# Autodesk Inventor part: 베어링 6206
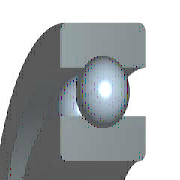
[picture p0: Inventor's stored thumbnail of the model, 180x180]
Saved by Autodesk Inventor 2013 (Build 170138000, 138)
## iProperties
Created: 2009-02
Part Number: 베어링 6206
Material: Steel, Mild
Description: 깊은 그루브 볼 베어링
Document SubType Name: Modeling
Standard: KS B 2023
Designer: KYOUNG IL JANG
Standards Organization: KS
Language: ko-KR
Size Designation: 6206 - 30 x 62 x 16
Categories: <MemberInstance><Categories><Category DisplayName="샤프트 부품" InternalName="7f7aeb1f-a693-4053-b835-cee3144e0d98" Mnemonic="SHFT"><Category DisplayName="베어링" Inter
Density: 1 g/cm^3
Company: 한국ATC센터
IsCustomPart: 0
Author: KYOUNG IL JANG
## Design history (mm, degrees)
sketch "스케치" dims "d0" = 8.32 (= -0.26 x WD + 0.26 x BD)
  geometry: L1 (3.84, 23)-(12.16, 23); L2 (8, 23)-(8, 18.84); L3 (8, 23)-(8, 27.16); L4 (4.909, 20.216)-(0, 20.216); L5 (0, 15)-(16, 15); L6 (4.909, 25.784)-(0, 25.784); L7 (0, 31)-(16, 31); L8 (16, 15)-(16, 20.216); L9 (11.091, 20.216)-(16, 20.216); L10 (11.091, 25.784)-(16, 25.784); L11 (16, 31)-(16, 25.784); L12 (-1.4, 0)-(8.4, 0) reference; L13 (0, -0.3)-(0, 5.3) reference
  constraints: 22 end point, 4 point on line, 2 collinear, 2 perpendicular, 2 symmetric about line, 1 midpoint, 1 parallel, 14 other
  dimensions: "d9" = 30 diameter of L5 L12 (= WD); "d11" = 62 diameter of L7 L12 (= BD); "d12" = 16 distance between parallel lines of L8 L13 (= KB); "d13" = 40.432 diameter of L9 L12 (= 0.326 x BD + 0.674 x WD)
revolve "본체" stored, may be unused: angle "d6" = 90 deg
revolve "볼" stored, may be unused: angle "d7" = 90 deg
pattern_circular "IDS_ARRAYBALL[SIMPL:T]" dims angle "d3" = 360 deg
body "Solid1"
fillet "모깎기1" dims "d1" = 1 (= KRS)
other parameters: "WD" = 30 [user parameter; used in 5 equation terms], "BD" = 62 [user parameter; used in 5 equation terms], "KB" = 16 [user parameter; used in 1 equation term], "KRS" = 1 [user parameter; used in 1 equation term], "d4" = 0, "d5" = 0, "d8" = 0, "d14" = 0, "d15" = 0, "BBA" = 0 [user parameter], "BC0" = 1.12e+07 [user parameter], "BC" = 1.95e+07 [user parameter], "BR" = 31 (= 0.5 x BD) [user parameter], "WR" = 15 (= 0.5 x WD) [user parameter]
